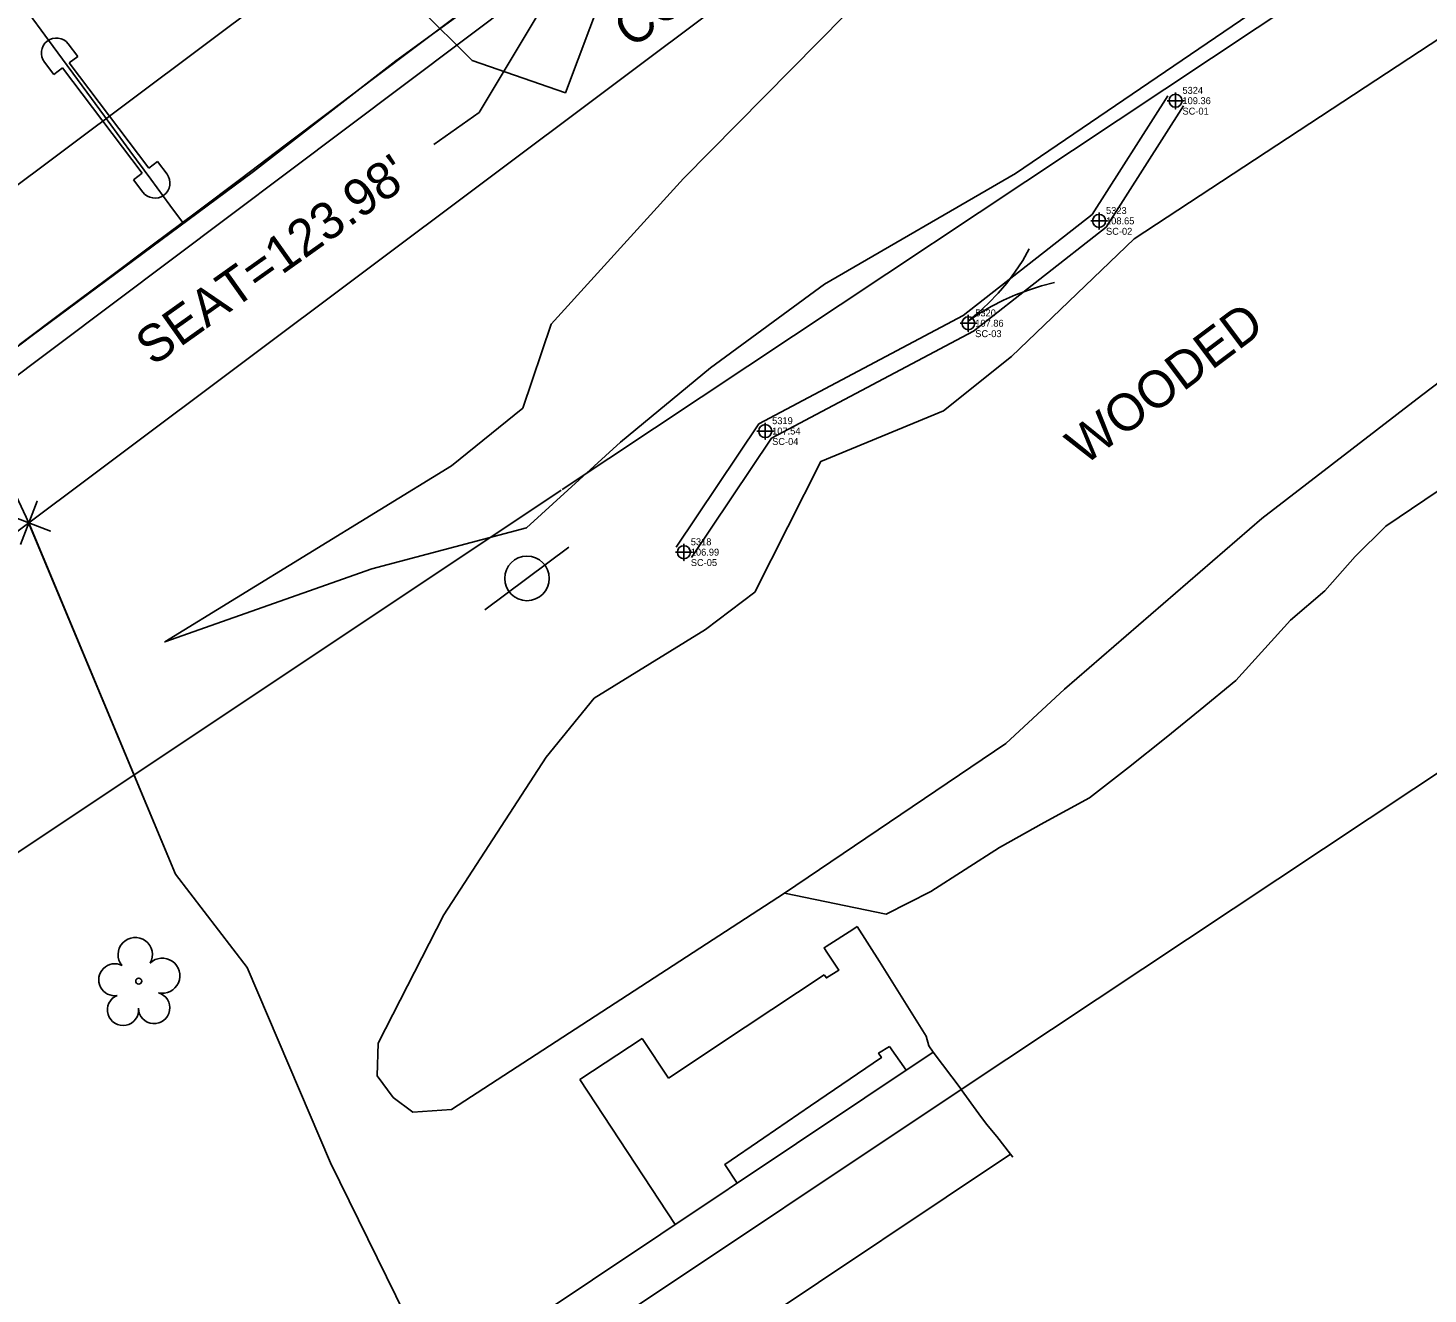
# Model space of a CAD drawing. Extents: x 2186615 to 2188822, y 629899 to 631820.
# Drawn here: x 2187792.7 to 2187944.2, y 630749.3 to 630886.3 of the extents above; entities that cross this region are included whole.
import ezdxf

# ---------------------------------------------------------------- set-up
doc = ezdxf.new("R2010")
doc.units = 0
for name, color, linetype in [('Exist Environmental Wetland Boundary Cogo Comment', 7, 'Continuous'), ('Exist Environmental Wetland Boundary Cogo Elevation', 7, 'Continuous'), ('Exist Environmental Wetland Boundary Cogo Number', 7, 'Continuous'), ('Exist Environmental Wetland Boundary Cogo Point CELL', 7, 'Continuous'), ('Exist Horizontal Alignment', 7, 'Continuous'), ('Exist Hydro Jurisdictional Stream or Body of Water', 7, 'Continuous'), ('Exist Hydro Stream Flow Arrow CELL', 7, 'Continuous'), ('Exist Other Culture Area Outline', 7, 'Continuous'), ('Exist Property Corner CELL', 7, 'Continuous'), ('Exist Property Line', 7, 'Continuous'), ('Exist Railroads Standard Gauge', 7, 'Continuous'), ('Exist Right of Way Line', 7, 'Continuous'), ('Exist Structure Major Bridge Seam', 7, 'Continuous'), ('Exist Structure Major Bridge Seat Leader', 7, 'Continuous'), ('Exist Structure Major Bridge Seat Top Elevation', 7, 'Continuous'), ('Exist Structure Major Bridge WW', 7, 'Continuous'), ('Exist Structure Major Bridge WW Text', 7, 'Continuous'), ('Exist Structure Major Deck Tunnel Box Culvert', 7, 'Continuous'), ('Exist Utilities Sanitary Sewer Forced Main SUE LOS B', 7, 'Continuous'), ('Exist Utilities Telephone Pole CELL', 7, 'Continuous'), ('Exist Vegetation Hedge Row', 7, 'Continuous'), ('Exist Vegetation Tree CELL', 7, 'Continuous'), ('Exist Vegetation Woods Line', 7, 'Continuous'), ('Exist Vegetation Woods Line Text', 7, 'Continuous'), ('Scratch_Level_1', 7, 'Continuous')]:
    doc.layers.add(name, color=color, linetype=linetype)

msp = doc.modelspace()

# ---------------------------------------------------------------- linework, layer by layer
at = {"layer": 'Exist Environmental Wetland Boundary Cogo Point CELL'}
for points in [[(2187916.9, 630879.32), (2187916.9, 630877.52), (2187916.9, 630878.42), (2187917.8, 630878.42), (2187916, 630878.42)], [(2187908.63, 630866.31), (2187908.63, 630864.51), (2187908.63, 630865.41), (2187909.53, 630865.41), (2187907.73, 630865.41)], [(2187894.48, 630855.23), (2187894.48, 630853.43), (2187894.48, 630854.33), (2187895.38, 630854.33), (2187893.58, 630854.33)], [(2187872.5, 630843.56), (2187872.5, 630841.76), (2187872.5, 630842.66), (2187873.4, 630842.66), (2187871.6, 630842.66)], [(2187863.7, 630830.45), (2187863.7, 630828.65), (2187863.7, 630829.55), (2187864.6, 630829.55), (2187862.8, 630829.55)]]:
    msp.add_lwpolyline(points, dxfattribs=at)
for centre in [(2187916.9, 630878.42), (2187908.63, 630865.41), (2187894.48, 630854.33), (2187872.5, 630842.66), (2187863.7, 630829.55)]:
    msp.add_circle(centre, 0.703, dxfattribs=at)
at = {"layer": 'Exist Horizontal Alignment'}
msp.add_line((2187136.41, 630378.11), (2188520.86, 631416.04), dxfattribs=at)
at = {"layer": 'Exist Hydro Jurisdictional Stream or Body of Water'}
for points in [[(2187808.69, 630794.71), (2187792.54, 630833.36), (2187781.22, 630857.42), (2187769.44, 630886.96), (2187764.08, 630902.91), (2187764.77, 630914.18), (2187760.54, 630924.3)], [(2187862.87, 630830.11), (2187871.81, 630843.43), (2187893.93, 630855.17), (2187907.88, 630866.09), (2187916.06, 630878.96)], [(2187864.53, 630828.99), (2187873.19, 630841.9), (2187895.03, 630853.49), (2187909.38, 630864.73), (2187917.75, 630877.88)], [(2187927.08, 630527.06), (2187917.72, 630546.8), (2187910.37, 630565.24), (2187902.17, 630594.17), (2187894.36, 630620.19), (2187881.92, 630652.4), (2187877.01, 630668.54), (2187859.29, 630698.24), (2187841.64, 630730.48), (2187825.46, 630763.45), (2187816.46, 630784.59), (2187808.69, 630794.71)]]:
    msp.add_lwpolyline(points, dxfattribs=at)
at = {"layer": 'Exist Hydro Stream Flow Arrow CELL'}
msp.add_line((2187898.45, 630857.56), (2187898.45, 630857.56), dxfattribs=at)
for points in [[(2187901.08, 630862.39), (2187900.37, 630861.11), (2187899.51, 630859.88), (2187898.64, 630858.68), (2187897.7, 630857.59), (2187896.67, 630856.52), (2187895.58, 630855.5), (2187894.45, 630854.56)], [(2187903.82, 630858.73), (2187902.39, 630858.4), (2187900.98, 630857.92), (2187899.58, 630857.42), (2187898.27, 630856.83), (2187896.95, 630856.14), (2187895.67, 630855.38), (2187894.45, 630854.56)]]:
    msp.add_lwpolyline(points, dxfattribs=at)
at = {"layer": 'Exist Other Culture Area Outline'}
for p, q in [((2187797.08, 630884.58), (2187798.11, 630883.22)), ((2187798.11, 630883.22), (2187797.17, 630882.51)), ((2187795.51, 630881.25), (2187794.5, 630882.59)), ((2187796.46, 630881.97), (2187795.51, 630881.25)), ((2187805.09, 630870.57), (2187796.46, 630881.97)), ((2187797.17, 630882.51), (2187805.81, 630871.12)), ((2187805.81, 630871.12), (2187806.75, 630871.83)), ((2187806.75, 630871.83), (2187807.78, 630870.47)), ((2187804.15, 630869.86), (2187805.09, 630870.57)), ((2187805.16, 630868.52), (2187804.15, 630869.86)), ((2187859.2, 630776.9), (2187852.45, 630772.48)), ((2187862.02, 630772.61), (2187859.2, 630776.9)), ((2187885.95, 630776.06), (2187887.75, 630773.47))]:
    msp.add_line(p, q, dxfattribs=at)
for points in [[(2187821.88, 630927.25), (2187817.99, 630925.54), (2187815.81, 630923), (2187814.96, 630918.81), (2187816.47, 630912.02), (2187820.24, 630903.82), (2187824.62, 630896.62), (2187828.79, 630891.96), (2187835.07, 630888.46), (2187840.78, 630882.77), (2187850.88, 630879.29), (2187854.91, 630889.95), (2187851.43, 630888.23), (2187848.23, 630889.48), (2187827.14, 630916.4), (2187826.15, 630919.95), (2187827.29, 630924.63), (2187821.88, 630927.25)], [(2187882.46, 630789.03), (2187881.98, 630788.7), (2187879.1, 630786.88), (2187878.87, 630786.73), (2187879.11, 630786.35)], [(2187878.89, 630783.79), (2187879.12, 630783.46), (2187880.47, 630784.32), (2187879.11, 630786.35)], [(2187878.89, 630783.79), (2187870.35, 630778.14), (2187862.02, 630772.61)], [(2187885.95, 630776.06), (2187884.77, 630775.34), (2187885.08, 630774.85), (2187877.39, 630769.62), (2187872.34, 630766.17), (2187868.14, 630763.28), (2187869.45, 630761.25)], [(2187862.75, 630756.78), (2187852.45, 630772.48)]]:
    msp.add_lwpolyline(points, dxfattribs=at)
for centre, start, end in [((2187795.8, 630883.57), 38.2035, 217.1439), ((2187806.46, 630869.51), 217.1439, 36.0842)]:
    msp.add_arc(centre, 1.63, start, end, dxfattribs=at)
at = {"layer": 'Exist Property Corner CELL'}
msp.add_line((2187792.82, 630832.73), (2187792.82, 630832.73), dxfattribs=at)
msp.add_lwpolyline([(2187790.48, 630833.63), (2187795.15, 630831.83), (2187792.82, 630832.73), (2187793.72, 630835.06), (2187791.92, 630830.4)], dxfattribs=at)
at = {"layer": 'Exist Property Line'}
msp.add_lwpolyline([(2187927.08, 630527.06), (2187917.72, 630546.8), (2187910.37, 630565.24), (2187902.17, 630594.17), (2187894.36, 630620.19), (2187881.92, 630652.4), (2187877.01, 630668.54), (2187859.29, 630698.24), (2187841.64, 630730.48), (2187825.46, 630763.45), (2187816.46, 630784.59), (2187808.69, 630794.71), (2187792.82, 630832.73)], dxfattribs=at)
at = {"layer": 'Exist Railroads Standard Gauge'}
for q in [(2188414.52, 631117.54), (2187662.94, 630617.46)]:
    msp.add_line((2187893.71, 630771.38), q, dxfattribs=at)
at = {"layer": 'Exist Right of Way Line'}
for p, q in [((2187154.4, 630354.1), (2188538.85, 631392.04)), ((2187850.54, 630836.34), (2188624.63, 631350.85)), ((2187850.54, 630836.34), (2188371.34, 631182.5)), ((2187850.54, 630836.34), (2188371.34, 631182.5)), ((2187522.53, 630617.66), (2187850.44, 630836.28))]:
    msp.add_line(p, q, dxfattribs=at)
at = {"layer": 'Exist Structure Major Bridge Seam'}
msp.add_lwpolyline([(2187792.87, 630887.81), (2187794.55, 630885.52), (2187795.97, 630883.6), (2187798.59, 630880.03), (2187801.02, 630876.74), (2187803.76, 630873.01), (2187806.03, 630869.92), (2187808.09, 630867.13), (2187809.45, 630865.28)], dxfattribs=at)
at = {"layer": 'Exist Structure Major Bridge Seat Leader'}
msp.add_lwpolyline([(2187850.96, 630892.87), (2187841.54, 630877.16), (2187836.65, 630873.69)], dxfattribs=at)
at = {"layer": 'Exist Structure Major Bridge WW'}
for points in [[(2187882.46, 630789.03), (2187884.88, 630785.25), (2187889.93, 630777.18), (2187890.22, 630776.13), (2187890.69, 630775.43), (2187893.69, 630771.42), (2187893.71, 630771.38)], [(2187893.71, 630771.38), (2187895.63, 630768.77)], [(2187895.63, 630768.77), (2187896.45, 630767.62), (2187897.57, 630766.29), (2187899.04, 630764.39)], [(2187899.04, 630764.39), (2187899.3, 630764.05)]]:
    msp.add_lwpolyline(points, dxfattribs=at)
at = {"layer": 'Exist Structure Major Deck Tunnel Box Culvert'}
for p, q in [((2187852.33, 630894.37), (2187601.73, 630705.99)), ((2187660.16, 630621.51), (2187890.69, 630775.43)), ((2187668.02, 630609.98), (2187899.04, 630764.39))]:
    msp.add_line(p, q, dxfattribs=at)
msp.add_lwpolyline([(2187839.72, 630888.05), (2187834.93, 630884.45), (2187830.13, 630880.84), (2187825.34, 630877.22), (2187820.56, 630873.61), (2187815.77, 630869.98), (2187810.98, 630866.37), (2187806.17, 630862.78), (2187801.37, 630859.19), (2187796.56, 630855.6), (2187791.76, 630852)], dxfattribs=at)
at = {"layer": 'Exist Utilities Sanitary Sewer Forced Main SUE LOS B'}
msp.add_lwpolyline([(2187639.4, 630737.18), (2187658.16, 630751.34), (2187676.41, 630765.17), (2187695.58, 630779.55), (2187713.95, 630793.24), (2187732.6, 630807.47), (2187751.11, 630821.21), (2187774.55, 630838.89), (2187793.19, 630853.01), (2187817.13, 630870.75), (2187832.54, 630882.73), (2187848.61, 630894.45), (2187859.56, 630897.68), (2187872.29, 630907.08), (2187904.19, 630928.23), (2187917.85, 630937.14), (2187951.64, 630961.53), (2187983.48, 630985.87), (2188013.42, 631007.09), (2188037.93, 631025.04), (2188052.05, 631035.58)], dxfattribs=at)
at = {"layer": 'Exist Utilities Telephone Pole CELL'}
for p, q in [((2187842.18, 630823.31), (2187851.26, 630830.1)), ((2187846.72, 630826.71), (2187846.72, 630826.71))]:
    msp.add_line(p, q, dxfattribs=at)
msp.add_circle((2187846.72, 630826.71), 2.41, dxfattribs=at)
at = {"layer": 'Exist Vegetation Hedge Row'}
msp.add_lwpolyline([(2187948.09, 630838.06), (2187939.67, 630832.38), (2187936.35, 630829.08), (2187933.05, 630825.38), (2187929.35, 630822.2), (2187923.43, 630815.66), (2187919.57, 630812.49), (2187915.87, 630809.51), (2187911.81, 630806.24), (2187907.58, 630802.97), (2187902.69, 630800.28), (2187897.87, 630797.57), (2187890.44, 630792.81), (2187885.6, 630790.38), (2187874.6, 630792.65)], dxfattribs=at)
at = {"layer": 'Exist Vegetation Tree CELL'}
msp.add_line((2187804.71, 630783.12), (2187804.71, 630783.12), dxfattribs=at)
msp.add_circle((2187804.71, 630783.12), 0.326, dxfattribs=at)
for centre, radius, start, end in [((2187804.33, 630785.99), 1.86, 330.1651, 219.7134), ((2187802.11, 630783.27), 1.73, 62.6636, 279.3457), ((2187807.26, 630783.71), 1.9, 257.1011, 134.1999), ((2187803.01, 630780), 1.69, 111.5671, 6.231), ((2187806.38, 630780.22), 1.7, 181.2822, 74.56)]:
    msp.add_arc(centre, radius, start, end, dxfattribs=at)
at = {"layer": 'Exist Vegetation Woods Line'}
for points in [[(2188336.81, 631162.74), (2188304.67, 631140.79), (2188253.49, 631107.84), (2188202.91, 631074.1), (2188139.41, 631031.67), (2188093.1, 631000.83), (2188032.1, 630960.3), (2187970.81, 630919.03), (2187899.6, 630870.56), (2187878.91, 630858.57), (2187866.57, 630849.5), (2187856.84, 630841.46), (2187846.68, 630832.19), (2187829.94, 630827.76), (2187807.52, 630819.83), (2187838.54, 630838.9), (2187846.29, 630845.15), (2187849.33, 630854.22), (2187863.66, 630870.01), (2187881.14, 630887.73), (2187900, 630901.47)], [(2188100.36, 630961.19), (2188067.24, 630937.46), (2188044.04, 630921.54), (2188015.4, 630902.33), (2187990.59, 630885.5), (2187967.82, 630864.96), (2187943.51, 630846.5), (2187926.23, 630833.19), (2187904.9, 630814.71), (2187898.54, 630808.83)], [(2187898.54, 630808.83), (2187874.6, 630792.65), (2187838.54, 630769.21), (2187834.36, 630768.93), (2187832.23, 630770.53), (2187830.51, 630772.86), (2187830.61, 630776.41), (2187837.73, 630790.3), (2187848.81, 630807.35), (2187853.98, 630813.75), (2187866.03, 630821.17), (2187871.37, 630825.21), (2187878.52, 630839.38), (2187891.78, 630844.86), (2187899.14, 630850.74), (2187912.42, 630863.47), (2187965.88, 630898.63)]]:
    msp.add_lwpolyline(points, dxfattribs=at)
at = {"layer": 'Scratch_Level_1'}
for p, q in [((2187893.71, 630771.38), (2188667.8, 631285.88)), ((2187565.8, 630552.76), (2187893.71, 630771.38))]:
    msp.add_line(p, q, dxfattribs=at)

# ---------------------------------------------------------------- texts
at = {"layer": 'Exist Environmental Wetland Boundary Cogo Comment'}
for s, p in [('SC-01', (2187917.65, 630876.92)), ('SC-02', (2187909.38, 630863.91)), ('SC-03', (2187895.23, 630852.83)), ('SC-04', (2187873.25, 630841.16)), ('SC-05', (2187864.45, 630828.05))]:
    msp.add_text(s, height=0.75, dxfattribs=at).set_placement(p)
at = {"layer": 'Exist Environmental Wetland Boundary Cogo Elevation'}
for s, p in [('109.36', (2187917.65, 630878.05)), ('108.65', (2187909.38, 630865.04)), ('107.86', (2187895.23, 630853.96)), ('107.54', (2187873.25, 630842.29)), ('106.99', (2187864.45, 630829.18))]:
    msp.add_text(s, height=0.75, dxfattribs=at).set_placement(p)
at = {"layer": 'Exist Environmental Wetland Boundary Cogo Number'}
for s, p in [('5324', (2187917.65, 630879.17)), ('5323', (2187909.38, 630866.16)), ('5320', (2187895.23, 630855.08)), ('5319', (2187873.25, 630843.41)), ('5318', (2187864.45, 630830.3))]:
    msp.add_text(s, height=0.75, dxfattribs=at).set_placement(p)
at = {"layer": 'Exist Structure Major Bridge Seat Top Elevation'}
msp.add_text("SEAT=123.98'", height=4, rotation=35.4068, dxfattribs=at).set_placement((2187806.25, 630849.62))
at = {"layer": 'Exist Structure Major Bridge WW Text'}
msp.add_text('CONC H/W', height=4, rotation=36.8593, dxfattribs=at).set_placement((2187858.07, 630883.98))
at = {"layer": 'Exist Vegetation Woods Line Text'}
msp.add_text('WOODED', height=4, rotation=36.8593, dxfattribs=at).set_placement((2187907.02, 630838.86))

doc.saveas('drawing.dxf')
